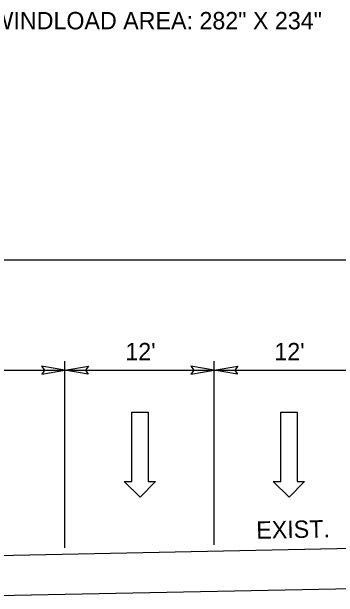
# Model space of a CAD drawing. Extents: x 1726790 to 1728895, y 539219 to 541550.
# Drawn here: x 1727265.4 to 1727397, y 541308.8 to 541545.1 of the extents above; entities that cross this region are included whole.
import ezdxf

# ---------------------------------------------------------------- set-up
doc = ezdxf.new("R2010")
doc.units = 0
for name, color, linetype in [('Default', 7, 'Continuous'), ('Typical Pavement Slope CELL', 7, 'Continuous'), ('Typical Pavement Slope Information CELL', 7, 'Continuous')]:
    doc.layers.add(name, color=color, linetype=linetype)

msp = doc.modelspace()

# ---------------------------------------------------------------- linework, layer by layer
at = {"layer": 'Default'}
for p, q in [((1727250.93, 541445), (1727880.5, 541445)), ((1727286.83, 541328.77), (1727286.83, 541404.16)), ((1727346.99, 541329.98), (1727346.99, 541404.16)), ((1727226.89, 541400.46), (1727286.94, 541400.46)), ((1727286.94, 541400.46), (1727346.99, 541400.46)), ((1727346.99, 541400.46), (1727407.04, 541400.46)), ((1727313.73, 541355.56), (1727313.73, 541383.56)), ((1727313.73, 541383.56), (1727320.33, 541383.56)), ((1727320.33, 541383.56), (1727320.33, 541355.56)), ((1727373.78, 541355.56), (1727373.78, 541383.56)), ((1727373.78, 541383.56), (1727380.38, 541383.56)), ((1727380.38, 541383.56), (1727380.38, 541355.56)), ((1727317.13, 541349.26), (1727310.73, 541355.56)), ((1727310.73, 541355.56), (1727313.73, 541355.56)), ((1727323.33, 541355.56), (1727317.13, 541349.26)), ((1727320.33, 541355.56), (1727323.33, 541355.56)), ((1727377.18, 541349.26), (1727370.78, 541355.56)), ((1727370.78, 541355.56), (1727373.78, 541355.56)), ((1727383.38, 541355.56), (1727377.18, 541349.26)), ((1727380.38, 541355.56), (1727383.38, 541355.56))]:
    msp.add_line(p, q, dxfattribs=at)
for points in [[(1727277.46, 541398.85), (1727286.83, 541400.46), (1727277.4, 541402.13), (1727278.6, 541400.46)], [(1727296.21, 541398.85), (1727286.83, 541400.46), (1727296.26, 541402.13), (1727295.07, 541400.46)], [(1727337.61, 541398.85), (1727346.99, 541400.46), (1727337.56, 541402.13), (1727338.76, 541400.46)], [(1727356.37, 541398.85), (1727346.99, 541400.46), (1727356.42, 541402.13), (1727355.22, 541400.46)]]:
    msp.add_lwpolyline(points, close=True, dxfattribs=at)
at = {"layer": 'Typical Pavement Slope CELL'}
for p, q in [((1727226.79, 541325.1), (1727461.04, 541329.79)), ((1727226.79, 541308.85), (1727461.04, 541313.53))]:
    msp.add_line(p, q, dxfattribs=at)

# ---------------------------------------------------------------- texts
at = {"layer": 'Typical Pavement Slope Information CELL'}
for s, height, p in [('WINDLOAD AREA: 282" X 234"', 7.0055, (1727257.21, 541537.98)), ("12'", 7.005, (1727311.15, 541404.47)), ("12'", 7.005, (1727371.2, 541404.47))]:
    msp.add_text(s, height=height, dxfattribs=at).set_placement(p)
msp.add_text('EXIST.', height=7.005, rotation=1.1457, dxfattribs=at).set_placement((1727363.97, 541332.45))

doc.saveas('drawing.dxf')
